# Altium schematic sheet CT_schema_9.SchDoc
size 278 x 170 mm
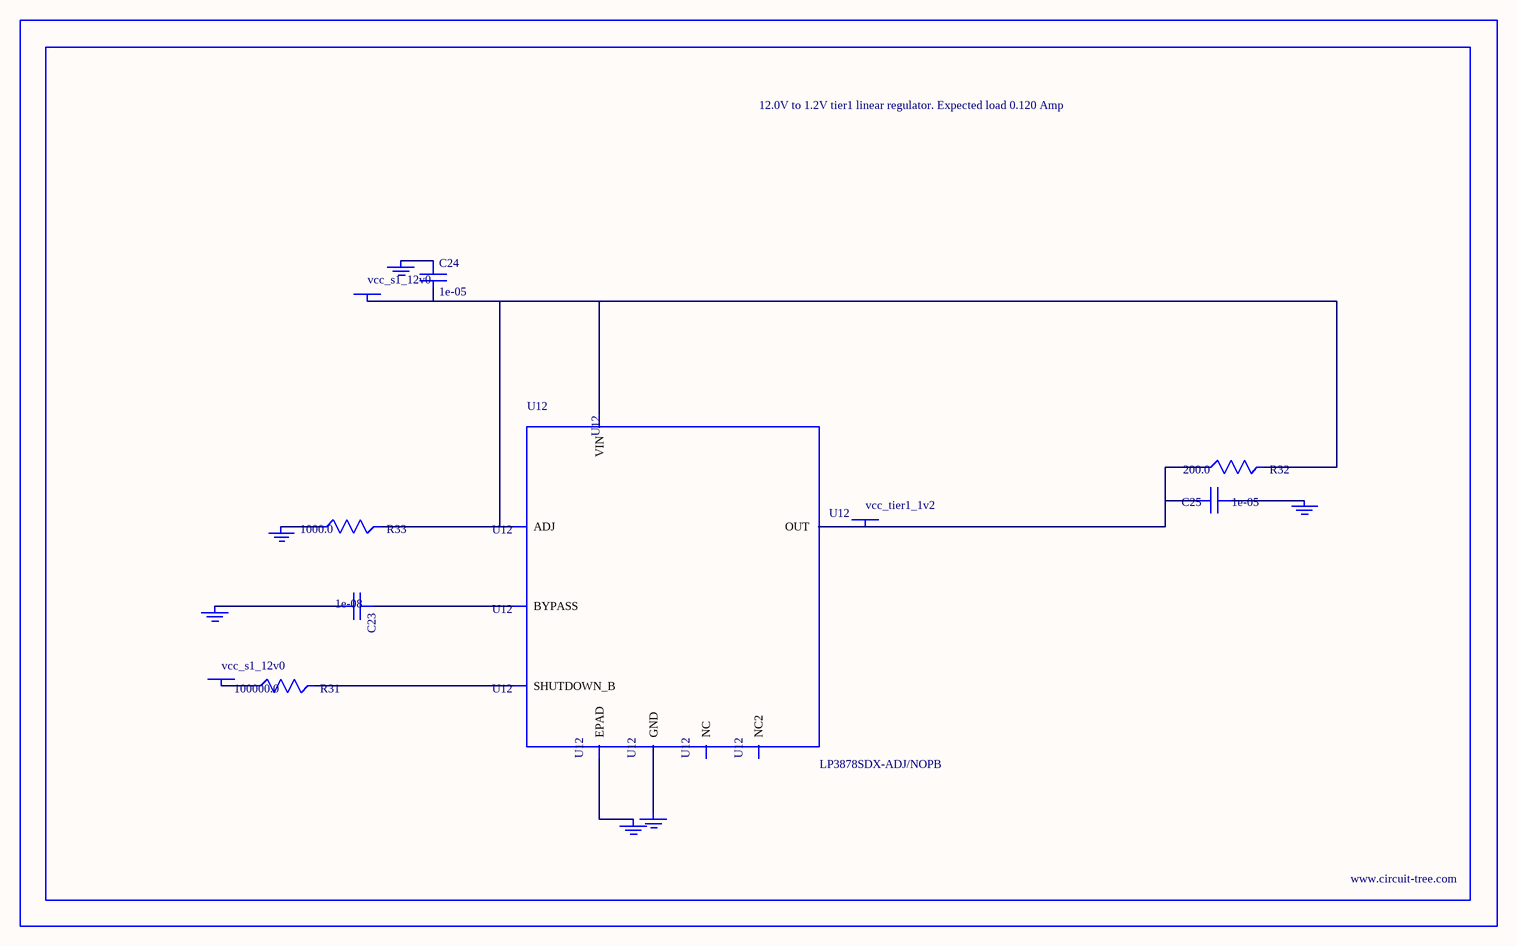
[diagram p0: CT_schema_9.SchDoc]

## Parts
BORDER8  (no value)
C23  1e-08  [C0402]
C24  1e-05  [C1210]
C25  1e-05  [C0805]
GND_INSTANCE_8_0  (no value)
GND_INSTANCE_8_1  (no value)
GND_INSTANCE_8_2  (no value)
GND_INSTANCE_8_3  (no value)
GND_INSTANCE_8_4  (no value)
GND_INSTANCE_8_5  (no value)
POWER_INSTANCE_8_0  vcc_s1_12v0
POWER_INSTANCE_8_1  vcc_s1_12v0
POWER_INSTANCE_8_2  vcc_tier1_1v2
R31  100000.0  [R0603]
R32  200.0  [R0603]
R33  1000.0  [R0603]
U12  LP3878SDX-ADJ/NOPB  [WSON-8]

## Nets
NetC23_1: C23.1 U12.1(BYPASS)
NetC23_2: C23.2 GND_INSTANCE_8_0.0(GND)
NetC24_1: C24.1 GND_INSTANCE_8_1.0(GND)
NetC24_2: C24.2 POWER_INSTANCE_8_0.0(PWR) R32.2 R33.2 U12.4(VIN) U12.6(ADJ)
NetC25_1: C25.1 GND_INSTANCE_8_2.0(GND)
NetC25_2: C25.2 POWER_INSTANCE_8_2.0(PWR) R32.1 U12.5(OUT)
NetGND_INSTANCE_8_3_0: GND_INSTANCE_8_3.0(GND) R33.1
NetGND_INSTANCE_8_4_0: GND_INSTANCE_8_4.0(GND) U12.PAD(EPAD)
NetGND_INSTANCE_8_5_0: GND_INSTANCE_8_5.0(GND) U12.3(GND)
NetPOWER_INSTANCE_8_1_0: POWER_INSTANCE_8_1.0(PWR) R31.1
NetR31_2: R31.2 U12.8(SHUTDOWN_B)

Not connected (* = marked no-connect by the designer): U12 2(NC) 7(NC2)

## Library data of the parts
BORDER8 = BORDER_PAGE8
C23 = C0402C103K3RAC
C24 = C1210C106K5PACTU
C25 = GRM219R60J106ME19D
GND_INSTANCE_8_0-GND_INSTANCE_8_5 = GND
POWER_INSTANCE_8_0-POWER_INSTANCE_8_2 = PWR
R31 = RC0603JR-07100KL
R32 = RC0603JR-07200RL
R33 = RC0603JR-071KL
